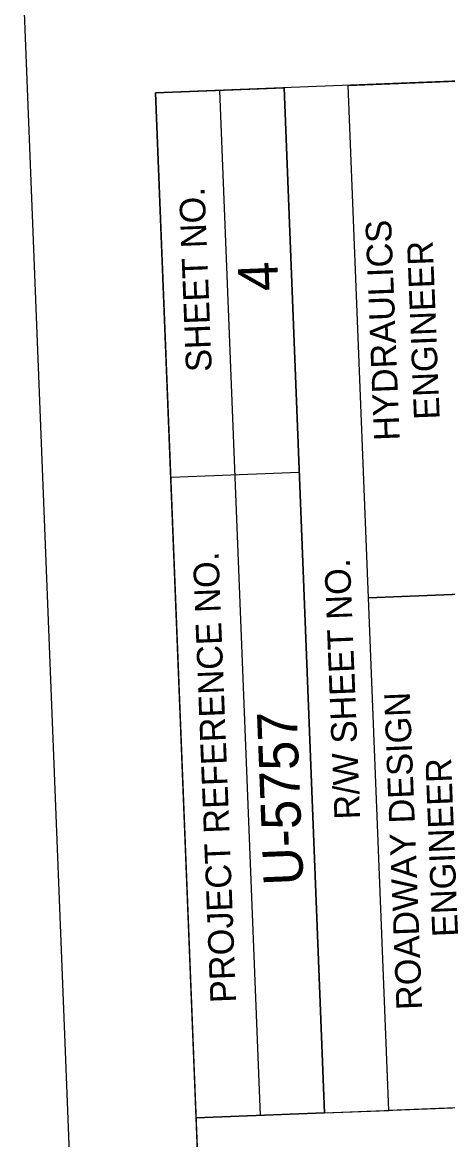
# Model space of a CAD drawing. Extents: x 1627905 to 1629071, y 761064 to 763101.
# Drawn here: x 1627905.2 to 1627988, y 762646.9 to 762864.8 of the extents above; entities that cross this region are included whole.
import ezdxf

# ---------------------------------------------------------------- set-up
doc = ezdxf.new("R2010")
doc.units = 0
for name, color, linetype in [('Old_Level_58', 7, 'Continuous'), ('Sheet Data Field CELL', 7, 'Continuous'), ('Sheet Plan And Profile CELL', 7, 'Continuous'), ('Sheet Plot Border Outside CELL', 7, 'Continuous')]:
    doc.layers.add(name, color=color, linetype=linetype)

msp = doc.modelspace()

# ---------------------------------------------------------------- linework, layer by layer
at = {"layer": 'Old_Level_58'}
msp.add_lwpolyline([(1627946.91, 762451.28), (1627939.02, 762651.17), (1628005.66, 762653.8), (1628013.55, 762453.91)], close=True, dxfattribs=at)
at = {"layer": 'Sheet Plan And Profile CELL'}
for p, q in [((1627951.56, 762651.67), (1627943.68, 762851.56)), ((1627964.05, 762652.16), (1627956.17, 762852.06)), ((1627934.15, 762776.13), (1627959.13, 762777.11)), ((1627972.6, 762752.63), (1628084.97, 762757.06)), ((1627964.05, 762652.16), (1627976.55, 762652.65))]:
    msp.add_line(p, q, dxfattribs=at)
for points in [[(1627931.14, 762851.07), (1627990.25, 761352.23), (1629039.43, 761393.61), (1628980.33, 762892.44)], [(1627972.6, 762752.63), (1627968.66, 762852.55), (1628081.08, 762856.98), (1628085.02, 762757.06)], [(1627939.02, 762651.17), (1627931.14, 762851.07), (1627956.17, 762852.06), (1627964.05, 762652.16)], [(1627976.55, 762652.65), (1627972.6, 762752.63), (1628085.02, 762757.06), (1628088.96, 762657.09)]]:
    msp.add_lwpolyline(points, close=True, dxfattribs=at)
at = {"layer": 'Sheet Plot Border Outside CELL'}
msp.add_lwpolyline([(1629071.31, 761219.73), (1629004.32, 762918.41), (1627905.18, 762875.06), (1627972.16, 761176.38)], close=True, dxfattribs=at)

# ---------------------------------------------------------------- texts
at = {"layer": 'Sheet Data Field CELL'}
for s, p in [('4', (1627955.08, 762812.53)), ('U-5757', (1627959.95, 762696.65))]:
    msp.add_text(s, height=7.75, rotation=92.2582, dxfattribs=at).set_placement(p)
at = {"layer": 'Sheet Plan And Profile CELL'}
for s, height, p in [('SHEET NO.', 5, (1627942.09, 762796.76)), ('HYDRAULICS', 5, (1627978.7, 762783.34)), ('ENGINEER', 5, (1627986.49, 762787.45)), ('PROJECT REFERENCE NO.', 5.0001, (1627946.84, 762673.7)), ('R/W SHEET NO.', 5.0001, (1627971, 762709.48)), ('ROADWAY DESIGN', 5.0001, (1627983.08, 762672.33)), ('ENGINEER', 5, (1627990.07, 762686.56))]:
    msp.add_text(s, height=height, rotation=92.2582, dxfattribs=at).set_placement(p)

doc.saveas('drawing.dxf')
